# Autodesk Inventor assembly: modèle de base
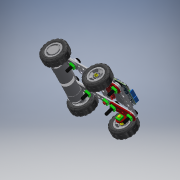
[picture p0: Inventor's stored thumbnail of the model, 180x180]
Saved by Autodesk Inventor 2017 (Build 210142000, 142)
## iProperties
Part Number: modèle de base
Material: Générique
Document SubType Name: Assembly
Designer: ficho
Author: ficho
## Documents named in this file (4)
- G:\travail\année 2017-2018\1STI2D\challenge\modèle de base.iam
- G:\travail\année 2017-2018\1STI2D\challenge\ensemble axe jante roue.iam
- G:\travail\année 2017-2018\1STI2D\challenge\roue libre.iam
- G:\travail\année 2017-2018\1STI2D\challenge\structure de base.iam
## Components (5 placed, 3 different names)
1. ensemble axe jante roue:1 [sub-assembly] — Logement:3
2. ensemble axe jante roue:2 [sub-assembly] — Logement:4
3. roue libre:1 [sub-assembly] — Logement:2
4. roue libre:2 [sub-assembly] — Logement:1
5. structure de base:1 [sub-assembly] — Logement:1, Logement:2, Logement:3, Logement:4
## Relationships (4: Insert 4)
- Logement:1 [Insert]: roue libre:2 ↔ structure de base:1
- Logement:2 [Insert]: roue libre:1 ↔ structure de base:1
- Logement:3 [Insert]: ensemble axe jante roue:1 ↔ structure de base:1
- Logement:4 [Insert]: ensemble axe jante roue:2 ↔ structure de base:1
